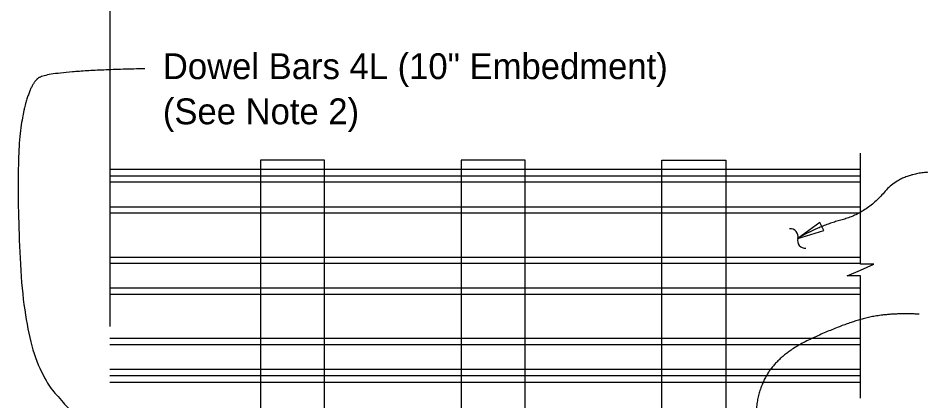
# Model space of a CAD drawing. Extents: x 1.5 to 68.7, y 0 to 31.
# Drawn here: x 5.82 to 12.85, y 13.32 to 16.3 of the extents above; entities that cross this region are included whole.
import ezdxf

# ---------------------------------------------------------------- set-up
doc = ezdxf.new("R2010")
doc.units = 0
doc.layers.add('Dimension', color=7, linetype='Continuous')
doc.layers.add('Miscellaneous', color=7, linetype='Continuous')

msp = doc.modelspace()

# ---------------------------------------------------------------- linework, layer by layer
at = {"layer": 'Dimension'}
msp.add_lwpolyline([(12.3808, 13.3413), (12.3808, 14.2947), (12.2775, 14.2947), (12.3808, 14.3397), (12.4842, 14.3847), (12.3808, 14.3847), (12.3808, 15.2514)], dxfattribs=at)
msp.add_lwpolyline([(11.893, 14.5864), (12.0953, 14.6471), (12.0641, 14.7103)], close=True, dxfattribs=at)
for centre, start, end in [((11.8359, 14.602), 344.25937, 95.98659), ((11.9507, 14.5696), 164.25937, 275.98659)]:
    msp.add_arc(centre, 0.0596, start, end, dxfattribs=at)
for points in [[(6.8093, 15.9088), (6.0612, 15.8929), (5.9024, 15.7817), (5.8017, 15.236), (5.8706, 13.668), (6.3154, 13.1303), (6.7761, 12.8283), (7.0775, 12.6089)], [(12.9919, 15.1029), (12.706, 15.1121), (12.429, 14.7831), (12.0627, 14.6848), (11.8929, 14.5864)], [(12.837, 13.9956), (12.5596, 14.0093), (12.1826, 13.8927), (11.762, 13.6895), (11.5665, 13.3921), (11.5665, 12.9582), (11.0189, 12.8991), (10.5496, 12.8912)]]:
    msp.add_open_spline(points, degree=2, dxfattribs=at)
at = {"layer": 'Miscellaneous'}
for p, q in [((6.5373, 21.2192), (6.5373, 13.8998)), ((6.5374, 15.1264), (12.3833, 15.1264)), ((6.5374, 15.0742), (12.3833, 15.0742)), ((6.5374, 15.026), (12.3833, 15.026)), ((6.5374, 14.8332), (12.3833, 14.8332)), ((6.5374, 14.7849), (12.3833, 14.7849)), ((6.5374, 14.441), (12.3833, 14.441)), ((6.5374, 14.3928), (12.3833, 14.3928)), ((6.5374, 14.1999), (12.3833, 14.1999)), ((6.5374, 14.1518), (12.3833, 14.1518)), ((6.5374, 13.8079), (12.3833, 13.8079)), ((6.5374, 13.7596), (12.3833, 13.7596)), ((6.5374, 13.5668), (12.3833, 13.5668)), ((6.5374, 13.5186), (12.3833, 13.5186)), ((6.5374, 13.4663), (12.3833, 13.4663))]:
    msp.add_line(p, q, dxfattribs=at)
for points in [[(8.2082, 11.3761), (8.2082, 15.1963), (7.7082, 15.1963), (7.7082, 11.3761)], [(9.7707, 11.3761), (9.7707, 15.1963), (9.2707, 15.1963), (9.2707, 11.3761)], [(10.8332, 11.3761), (10.8332, 15.1963), (11.3332, 15.1963), (11.3332, 11.3761)]]:
    msp.add_lwpolyline(points, dxfattribs=at)

# ---------------------------------------------------------------- texts
at = {"layer": 'Dimension'}
for s, p in [('Dowel Bars 4L (10" Embedment) ', (6.9491, 15.8279)), ('(See Note 2)', (6.9491, 15.4759))]:
    msp.add_text(s, height=0.2016, dxfattribs=at).set_placement(p)

doc.saveas('drawing.dxf')
